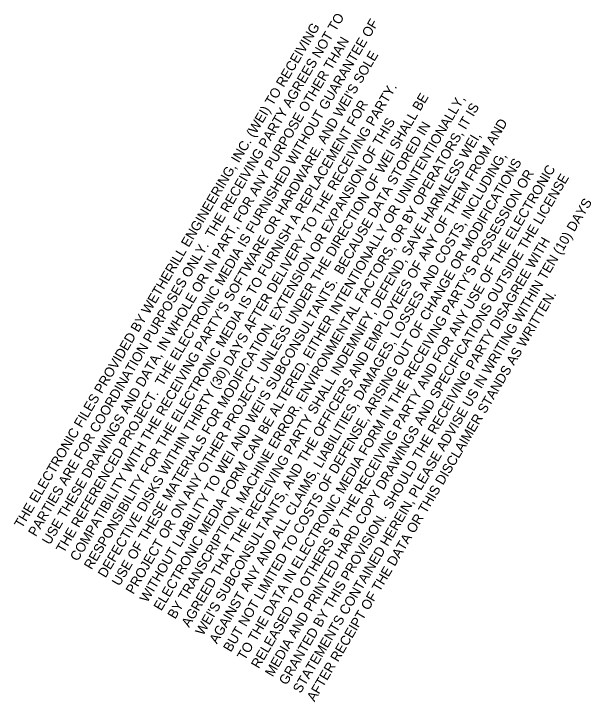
# Model space of a CAD drawing. Extents: x 2137594 to 2141353, y 404857 to 410633.
# Drawn here: x 2137594 to 2138945, y 404857 to 406469 of the extents above; entities that cross this region are included whole.
import ezdxf

# ---------------------------------------------------------------- set-up
doc = ezdxf.new("R2010")
doc.units = 0
doc.layers.add('Default', color=7, linetype='Continuous')

msp = doc.modelspace()

# ---------------------------------------------------------------- texts
at = {"layer": 'Default'}
for s, p in [('PARTIES ARE FOR COORDINATION PURPOSES ONLY.  THE RECEIVING PARTY AGREES NOT TO ', (2137645.7, 405243.3)), ('THE REFERENCED PROJECT.  THE ELECTRONIC MEDIA IS FURNISHED WITHOUT GUARANTEE OF ', (2137710.9, 405204.7)), ('THE ELECTRONIC FILES PROVIDED BY WETHERILL ENGINEERING, INC. (WEI) TO RECEIVING ', (2137613.2, 405262.6)), ('USE THESE DRAWINGS AND DATA, IN WHOLE OR IN PART, FOR ANY PURPOSE OTHER THAN ', (2137678.3, 405224)), ("COMPATIBILITY WITH THE RECEIVING PARTY'S SOFTWARE OR HARDWARE, AND WEI'S SOLE ", (2137743.5, 405185.4)), ('DEFECTIVE DISKS WITHIN THIRTY (30) DAYS AFTER DELIVERY TO THE RECEIVING PARTY.  ', (2137808.7, 405146.7)), ('PROJECT OR ON ANY OTHER PROJECT, UNLESS UNDER THE DIRECTION OF WEI SHALL BE ', (2137873.9, 405108.1)), ('ELECTRONIC MEDIA FORM CAN BE ALTERED, EITHER INTENTIONALLY OR UNINTENTIONALLY, ', (2137939.1, 405069.4)), ('RESPONSIBILITY FOR THE ELECTRONIC MEDIA IS TO FURNISH A REPLACEMENT FOR ', (2137776.1, 405166)), ('BY TRANSCRIPTION, MACHINE ERROR, ENVIRONMENTAL FACTORS, OR BY OPERATORS, IT IS ', (2137971.7, 405050.1)), ('USE OF THESE MATERIALS FOR MODIFICATION, EXTENSION OR EXPANSION OF THIS ', (2137841.3, 405127.4)), ("WITHOUT LIABILITY TO WEI AND WEI'S SUBCONSULTANTS.  BECAUSE DATA STORED IN ", (2137906.5, 405088.8)), ("WEI'S SUBCONSULTANTS, AND THE OFFICERS AND EMPLOYEES OF ANY OF THEM FROM AND ", (2138036.8, 405011.5)), ('AGREED THAT THE RECEIVING PARTY SHALL INDEMNIFY, DEFEND, SAVE HARMLESS WEI, ', (2138004.2, 405030.8)), ('AGAINST ANY AND ALL CLAIMS, LIABILITIES, DAMAGES, LOSSES AND COSTS, INCLUDING, ', (2138069.4, 404992.1)), ('BUT NOT LIMITED TO COSTS OF DEFENSE, ARISING OUT OF CHANGE OR MODIFICATIONS ', (2138102, 404972.8)), ('RELEASED TO OTHERS BY THE RECEIVING PARTY AND FOR ANY USE OF THE ELECTRONIC ', (2138167.2, 404934.2)), ("TO THE DATA IN ELECTRONIC MEDIA FORM IN THE RECEIVING PARTY'S POSSESSION OR ", (2138134.6, 404953.5)), ('MEDIA AND PRINTED HARD COPY DRAWINGS AND SPECIFICATIONS OUTSIDE THE LICENSE ', (2138199.8, 404914.9)), ('STATEMENTS CONTAINED HEREIN, PLEASE ADVISE US IN WRITING WITHIN TEN (10) DAYS ', (2138265, 404876.2)), ('GRANTED BY THIS PROVISION.  SHOULD THE RECEIVING PARTY DISAGREE WITH ', (2138232.4, 404895.5)), ('AFTER RECEIPT OF THE DATA OR THIS DISCLAIMER STANDS AS WRITTEN.', (2138297.6, 404856.9))]:
    msp.add_text(s, height=22.733, rotation=59.3391, dxfattribs=at).set_placement(p)

doc.saveas('drawing.dxf')
